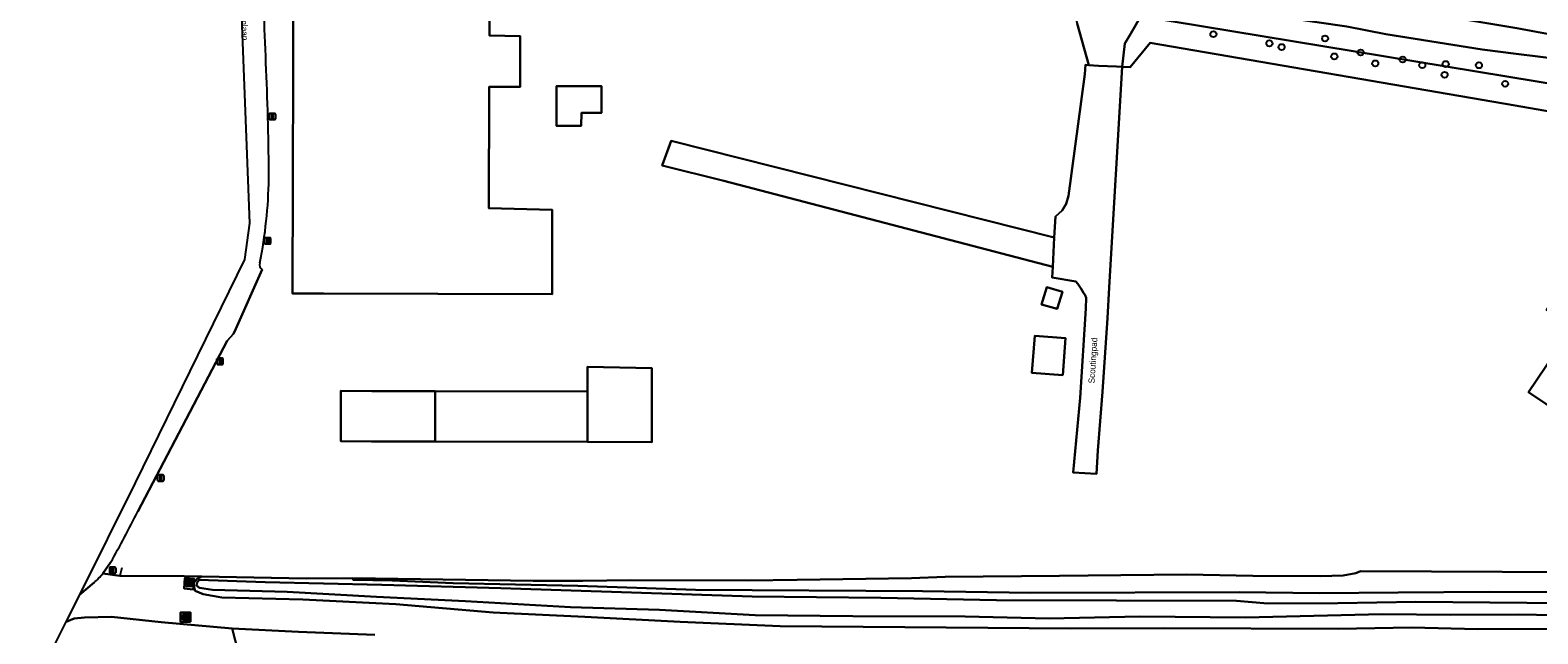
# Model space of a CAD drawing. Extents: x 162156 to 163172, y 378995 to 380779.
# Drawn here: x 162165.5 to 162409.9, y 379596.5 to 379694.4 of the extents above; entities that cross this region are included whole.
import ezdxf

# ---------------------------------------------------------------- set-up
doc = ezdxf.new("R2010")
doc.units = 0
for name, color, linetype in [('IMGEO_Boom', 7, 'Continuous'), ('IMGEO_Erf', 7, 'Continuous'), ('IMGEO_Fietspad_gesloten', 7, 'Continuous'), ('IMGEO_Grasland_overig', 7, 'Continuous'), ('IMGEO_Groenvoorziening', 7, 'Continuous'), ('IMGEO_Hek', 7, 'Continuous'), ('IMGEO_Lichtmast', 7, 'Continuous'), ('IMGEO_Loofbos', 7, 'Continuous'), ('IMGEO_Muur', 7, 'Continuous'), ('IMGEO_Open_loods', 7, 'Continuous'), ('IMGEO_Openbare_ruimte_label', 7, 'Continuous'), ('IMGEO_Pand', 7, 'Continuous'), ('IMGEO_Rijbaan_lokaal_gesloten', 7, 'Continuous'), ('IMGEO_Rijbaan_lokaal_onverhard', 7, 'Continuous'), ('IMGEO_Rijbaan_lokaal_open', 7, 'Continuous'), ('IMGEO_Rioolput', 7, 'Continuous'), ('IMGEO_Terreindeel_open', 7, 'Continuous'), ('IMGEO_Voetpad_open', 7, 'Continuous'), ('IMGEO_Waterloop', 7, 'Continuous')]:
    doc.layers.add(name, color=color, linetype=linetype)

msp = doc.modelspace()

# ---------------------------------------------------------------- linework, layer by layer
at = {"layer": 'IMGEO_Boom'}
for centre in [(162357.34, 379693.7), (162366.41, 379692.22), (162375.45, 379693.01), (162368.4, 379691.61), (162376.94, 379690.1), (162381.21, 379690.74), (162388.02, 379689.6), (162383.58, 379688.97), (162391.2, 379688.68), (162394.81, 379687.12), (162394.99, 379688.86), (162400.38, 379688.66), (162404.63, 379685.66)]:
    msp.add_circle(centre, 0.489, dxfattribs=at)
at = {"layer": 'IMGEO_Erf'}
for points in [[(162240, 379697.22), (162239.99, 379693.48), (162244.97, 379693.37), (162244.95, 379685.17), (162239.96, 379685.18), (162239.96, 379684.79), (162239.91, 379665.52), (162250.18, 379665.21), (162250.14, 379651.57), (162213.07, 379651.67), (162208.07, 379651.68), (162208.22, 379706.6)], [(162422.68, 379679.3), (162406.24, 379682.12), (162347.07, 379692.29), (162343.87, 379688.35), (162342.56, 379688.42), (162340.42, 379652.66), (162340.16, 379647.64), (162339.34, 379635.71), (162338.58, 379626.21), (162338.38, 379622.42), (162334.62, 379622.62), (162335.73, 379634.73), (162336.64, 379649.22), (162336.73, 379650.95), (162336.54, 379651.37), (162336.31, 379651.77), (162335.93, 379652.43), (162335.39, 379653.25), (162335.02, 379653.62), (162331.2, 379654.23), (162331.29, 379655.97), (162277.99, 379669.94), (162268.01, 379672.39), (162269.44, 379676.44), (162331.54, 379660.72), (162331.72, 379664.12), (162332.81, 379665.1), (162333.45, 379666.21), (162333.87, 379667.51), (162336.51, 379687.23), (162336.59, 379688.71), (162337.17, 379688.68), (162335.24, 379695.41)], [(162203.16, 379655.54), (162198.9, 379645.91), (162198.5, 379645.14), (162197.49, 379644), (162183.01, 379616.32)], [(162178.58, 379608.03), (162177.32, 379606.25), (162180.07, 379605.9), (162190.49, 379605.85), (162193.39, 379605.8), (162210.27, 379605.48), (162217.87, 379605.5), (162247.08, 379605.1), (162255.15, 379605.08), (162262.9, 379605.2), (162282.05, 379605.15), (162289.85, 379605.22), (162308.4, 379605.53), (162313.87, 379605.74), (162332.41, 379605.9), (162337.03, 379605.95), (162352.96, 379606.09), (162363.72, 379605.88), (162374.72, 379605.85), (162378.4, 379605.96), (162380.44, 379606.31), (162381.21, 379606.63), (162576.44, 379605.74)]]:
    msp.add_lwpolyline(points, dxfattribs=at)
for points in [[(162254.88, 379678.83), (162250.86, 379678.84), (162250.88, 379685.29), (162258.15, 379685.27), (162258.14, 379680.95), (162254.89, 379680.96)], [(162415.52, 379646.14), (162411.33, 379649.02), (162421.29, 379663.64), (162425.48, 379660.81), (162425.79, 379661.28), (162429.79, 379658.54), (162430.06, 379657.09), (162431.71, 379655.98), (162433.15, 379656.25), (162441.34, 379650.7), (162431.1, 379635.6), (162426.95, 379638.44), (162419.81, 379628), (162408.42, 379635.69)], [(162332.03, 379649.15), (162329.49, 379649.9), (162330.33, 379652.7), (162332.86, 379651.95)], [(162332.92, 379638.41), (162327.93, 379638.8), (162328.4, 379644.79), (162333.38, 379644.4)], [(162266.29, 379627.56), (162255.86, 379627.59), (162231.19, 379627.66), (162220.89, 379627.68), (162215.89, 379627.7), (162215.91, 379635.86), (162220.91, 379635.84), (162231.21, 379635.82), (162255.88, 379635.75), (162255.89, 379639.75), (162266.32, 379639.54)]]:
    msp.add_lwpolyline(points, close=True, dxfattribs=at)
for centre, radius, start, end in [((161851.59, 379678.49), 352.33, 1.5364, 4.4027), ((161695.6, 379666.41), 508.66, 0.4352, 2.4254), ((162126.57, 379671.65), 77.68, 348.8463, 358.9849), ((162203.65, 379656.31), 0.915, 160.322, 237.814), ((161991.49, 379713.35), 214.7, 330.6237, 333.1309)]:
    msp.add_arc(centre, radius, start, end, dxfattribs=at)
at = {"layer": 'IMGEO_Fietspad_gesloten'}
msp.add_lwpolyline([(162293.88, 379713.56), (162297.83, 379712.83), (162406.51, 379694.67), (162426.26, 379691.02), (162431.74, 379689.86)], dxfattribs=at)
at = {"layer": 'IMGEO_Grasland_overig'}
for points in [[(162431.74, 379689.86), (162426.26, 379691.02), (162406.51, 379694.67), (162297.83, 379712.83)], [(162336.99, 379698.76), (162343.52, 379698.34), (162344.24, 379698.95), (162346.34, 379699.64), (162347.96, 379699.34), (162359.67, 379698.01), (162369.63, 379696.28), (162378.99, 379694.93), (162385.27, 379693.71), (162400.92, 379691.22), (162406.42, 379690.54), (162420.47, 379688.81)]]:
    msp.add_lwpolyline(points, dxfattribs=at)
at = {"layer": 'IMGEO_Groenvoorziening'}
for points in [[(162430.28, 379682.33), (162429.51, 379682.78), (162345.56, 379696.61), (162344.76, 379695.24), (162343.93, 379693.83), (162342.98, 379692.21), (162342.56, 379688.42), (162343.87, 379688.35), (162347.07, 379692.29), (162406.24, 379682.12), (162422.68, 379679.3), (162423.76, 379680.09), (162427.17, 379682.58)], [(162192.09, 379604.77), (162191.99, 379603.7), (162190.5, 379603.81), (162190.63, 379605.52), (162192.11, 379605.41)], [(162191.55, 379598.45), (162189.92, 379598.44), (162189.91, 379599.95), (162191.54, 379599.97)], [(162165.54, 379587.07), (162171.56, 379586.89), (162171.57, 379589.2), (162172.13, 379590.83), (162172.89, 379591.55), (162173.82, 379591.75), (162175.52, 379591.81), (162183.9, 379591.47), (162193.2, 379590.46), (162200.18, 379590.02), (162198.3, 379597.35), (162186.78, 379598.4), (162178.75, 379599.23), (162174.33, 379599.15), (162172.66, 379598.95), (162171.36, 379598.45), (162171.31, 379598.43), (162167.11, 379590.02)]]:
    msp.add_lwpolyline(points, close=True, dxfattribs=at)
for points in [[(162175.92, 379604.79), (162173.52, 379602.83), (162171.31, 379598.43), (162171.36, 379598.45), (162172.66, 379598.95), (162174.33, 379599.15), (162178.75, 379599.23), (162186.78, 379598.4), (162198.3, 379597.35), (162209.04, 379596.79), (162221.4, 379596.34)], [(162192.09, 379604.77), (162192.6, 379605.42), (162193.39, 379605.8), (162190.49, 379605.85), (162180.07, 379605.9), (162177.32, 379606.25)], [(162417.45, 379603.23), (162402.03, 379603.27), (162387.27, 379603.21), (162374.55, 379603.06), (162361.54, 379603.25), (162327.73, 379603.12), (162310.18, 379603.38), (162273.39, 379603.64), (162254.33, 379604.29), (162234.09, 379604.68), (162224.23, 379605.14), (162217.88, 379605.23), (162217.87, 379605.5), (162210.27, 379605.48), (162193.39, 379605.8), (162192.6, 379605.42), (162192.09, 379604.77), (162192.12, 379604), (162192.29, 379603.47), (162193.56, 379602.9), (162196.6, 379602.38), (162209.76, 379602.03), (162224.79, 379601.29), (162240.59, 379599.92), (162255.44, 379599.26), (162270.89, 379598.43), (162287.14, 379597.73), (162334.23, 379597.34), (162349.3, 379597.38), (162377.58, 379597.27), (162389.47, 379597.5), (162400.18, 379597.26), (162422.68, 379597.35)], [(162422.68, 379597.35), (162400.18, 379597.26), (162389.47, 379597.5), (162377.58, 379597.27), (162349.3, 379597.38), (162334.23, 379597.34), (162287.14, 379597.73), (162270.89, 379598.43), (162255.44, 379599.26), (162240.59, 379599.92), (162224.79, 379601.29), (162209.76, 379602.03), (162196.6, 379602.38), (162193.56, 379602.9), (162192.29, 379603.47), (162192.12, 379604), (162192.09, 379604.77)], [(162429.76, 379599.2), (162406.83, 379599.61), (162395.85, 379599.58), (162384.71, 379599.68), (162362.52, 379599.13), (162345.43, 379599.3), (162330.73, 379598.97), (162317.12, 379599.28), (162298.89, 379599.34), (162283.05, 379599.52), (162267.53, 379600.4), (162253.15, 379600.81), (162236.09, 379601.8), (162221.69, 379602.47), (162207.2, 379603.27), (162195.11, 379603.61), (162192.98, 379603.96), (162192.5, 379604.34), (162192.59, 379604.82), (162192.93, 379605.24), (162203.62, 379604.86), (162222.57, 379604.41), (162241.81, 379603.9), (162282.56, 379602.52), (162303.45, 379602.33), (162322.16, 379601.93), (162361.11, 379601.84), (162366.19, 379601.41), (162377.5, 379601.47), (162390.14, 379601.66), (162450.09, 379601.12)], [(162576.44, 379605.74), (162381.21, 379606.63), (162380.44, 379606.31), (162378.4, 379605.96), (162374.72, 379605.85), (162363.72, 379605.88), (162352.96, 379606.09), (162337.03, 379605.95), (162332.41, 379605.9), (162313.87, 379605.74), (162308.4, 379605.53), (162289.85, 379605.22), (162282.05, 379605.15), (162262.9, 379605.2), (162255.15, 379605.08), (162247.08, 379605.1), (162217.87, 379605.5), (162217.88, 379605.23), (162224.23, 379605.14), (162234.09, 379604.68), (162254.33, 379604.29), (162273.39, 379603.64), (162310.18, 379603.38), (162327.73, 379603.12), (162361.54, 379603.25), (162374.55, 379603.06), (162387.27, 379603.21), (162402.03, 379603.27), (162417.45, 379603.23)], [(162221.4, 379596.34), (162209.04, 379596.79), (162198.3, 379597.35), (162200.18, 379590.02)]]:
    msp.add_lwpolyline(points, dxfattribs=at)
msp.add_arc((162166.58, 379615.14), 13.94, 312.0389, 320.3631, dxfattribs=at)
at = {"layer": 'IMGEO_Hek'}
for points in [[(162342.56, 379688.42), (162343.87, 379688.35), (162347.07, 379692.29), (162406.24, 379682.12)], [(162337.17, 379688.68), (162338.71, 379688.6)], [(162338.71, 379688.6), (162341.61, 379688.46)], [(162341.61, 379688.46), (162342.56, 379688.42)], [(162406.24, 379682.12), (162422.68, 379679.3), (162423.76, 379680.09)]]:
    msp.add_lwpolyline(points, dxfattribs=at)
at = {"layer": 'IMGEO_Lichtmast'}
for p, q in [((162204.31, 379679.96), (162204.31, 379680.76)), ((162204.31, 379680.76), (162204.31, 379679.96)), ((162204.41, 379680.86), (162205.2, 379680.86)), ((162205.2, 379680.86), (162204.41, 379680.86)), ((162205.3, 379680.76), (162205.3, 379679.96)), ((162205.3, 379679.96), (162205.3, 379680.76)), ((162205.2, 379679.86), (162204.41, 379679.86)), ((162204.41, 379679.86), (162205.2, 379679.86)), ((162203.54, 379659.8), (162203.54, 379660.6)), ((162203.54, 379660.6), (162203.54, 379659.8)), ((162203.64, 379660.7), (162204.42, 379660.7)), ((162204.42, 379660.7), (162203.64, 379660.7)), ((162204.52, 379660.6), (162204.52, 379659.8)), ((162204.52, 379659.8), (162204.52, 379660.6)), ((162204.42, 379659.7), (162203.64, 379659.7)), ((162203.64, 379659.7), (162204.42, 379659.7)), ((162195.8, 379640.26), (162195.8, 379641.06)), ((162195.8, 379641.06), (162195.8, 379640.26)), ((162195.9, 379641.16), (162196.69, 379641.16)), ((162196.69, 379641.16), (162195.9, 379641.16)), ((162196.79, 379641.06), (162196.79, 379640.26)), ((162196.79, 379640.26), (162196.79, 379641.06)), ((162196.69, 379640.16), (162195.9, 379640.16)), ((162195.9, 379640.16), (162196.69, 379640.16)), ((162186.21, 379621.35), (162186.21, 379622.15)), ((162186.21, 379622.15), (162186.21, 379621.35)), ((162186.31, 379622.25), (162187.1, 379622.25)), ((162187.1, 379622.25), (162186.31, 379622.25)), ((162187.2, 379622.15), (162187.2, 379621.35)), ((162187.2, 379621.35), (162187.2, 379622.15)), ((162187.1, 379621.25), (162186.31, 379621.25)), ((162186.31, 379621.25), (162187.1, 379621.25)), ((162178.44, 379606.39), (162178.44, 379607.19)), ((162178.44, 379607.19), (162178.44, 379606.39)), ((162178.54, 379607.29), (162179.33, 379607.29)), ((162179.33, 379607.29), (162178.54, 379607.29)), ((162179.43, 379607.19), (162179.43, 379606.39)), ((162179.43, 379606.39), (162179.43, 379607.19)), ((162179.33, 379606.29), (162178.54, 379606.29)), ((162178.54, 379606.29), (162179.33, 379606.29))]:
    msp.add_line(p, q, dxfattribs=at)
for points in [[(162204.73, 379680.73), (162204.88, 379680.73), (162204.88, 379679.98), (162204.73, 379679.98), (162204.73, 379680.73)], [(162203.96, 379660.57), (162204.11, 379660.57), (162204.11, 379659.82), (162203.96, 379659.82), (162203.96, 379660.57)], [(162196.22, 379641.04), (162196.37, 379641.04), (162196.37, 379640.29), (162196.22, 379640.29), (162196.22, 379641.04)], [(162186.63, 379622.12), (162186.78, 379622.12), (162186.78, 379621.37), (162186.63, 379621.37), (162186.63, 379622.12)], [(162178.86, 379607.16), (162179.01, 379607.16), (162179.01, 379606.41), (162178.86, 379606.41), (162178.86, 379607.16)]]:
    msp.add_lwpolyline(points, dxfattribs=at)
for centre, start, end in [((162204.41, 379680.76), 90, 180), ((162204.41, 379680.76), 90, 180), ((162205.2, 379680.76), 0, 90), ((162205.2, 379680.76), 360, 90), ((162204.41, 379679.96), 180, 270), ((162204.41, 379679.96), 180, 270), ((162205.2, 379679.96), 270, 0), ((162205.2, 379679.96), 270, 0), ((162203.64, 379660.6), 90, 180), ((162203.64, 379660.6), 90, 180), ((162204.42, 379660.6), 0, 90), ((162204.42, 379660.6), 360, 90), ((162203.64, 379659.8), 180, 270), ((162203.64, 379659.8), 180, 270), ((162204.42, 379659.8), 270, 0), ((162204.42, 379659.8), 270, 0), ((162195.9, 379641.06), 90, 180), ((162195.9, 379641.06), 90, 180), ((162196.69, 379641.06), 0, 90), ((162196.69, 379641.06), 360, 90), ((162195.9, 379640.26), 180, 270), ((162195.9, 379640.26), 180, 270), ((162196.69, 379640.26), 270, 0), ((162196.69, 379640.26), 270, 0), ((162186.31, 379622.15), 90, 180), ((162186.31, 379622.15), 90, 180), ((162187.1, 379622.15), 0, 90), ((162187.1, 379622.15), 360, 90), ((162186.31, 379621.35), 180, 270), ((162186.31, 379621.35), 180, 270), ((162187.1, 379621.35), 270, 0), ((162187.1, 379621.35), 270, 0), ((162178.54, 379607.19), 90, 180), ((162178.54, 379607.19), 90, 180), ((162179.33, 379607.19), 0, 90), ((162179.33, 379607.19), 360, 90), ((162178.54, 379606.39), 180, 270), ((162178.54, 379606.39), 180, 270), ((162179.33, 379606.39), 270, 0), ((162179.33, 379606.39), 270, 0)]:
    msp.add_arc(centre, 0.1, start, end, dxfattribs=at)
at = {"layer": 'IMGEO_Loofbos'}
msp.add_lwpolyline([(162420.47, 379688.81), (162406.42, 379690.54), (162400.92, 379691.22), (162385.27, 379693.71), (162378.99, 379694.93), (162369.63, 379696.28), (162359.67, 379698.01), (162347.96, 379699.34), (162346.34, 379699.64), (162344.24, 379698.95), (162343.52, 379698.34), (162346.47, 379698.15), (162345.56, 379696.61), (162429.51, 379682.78)], dxfattribs=at)
at = {"layer": 'IMGEO_Muur'}
for points in [[(162180.39, 379607.19), (162180.07, 379605.9)], [(162180.07, 379605.9), (162190.49, 379605.85), (162210.27, 379605.48), (162217.87, 379605.5), (162247.08, 379605.1), (162255.15, 379605.08), (162262.9, 379605.2), (162282.05, 379605.15), (162289.85, 379605.22), (162308.4, 379605.53), (162313.87, 379605.74), (162332.41, 379605.9)], [(162332.41, 379605.9), (162337.03, 379605.95)], [(162337.03, 379605.95), (162352.96, 379606.09), (162363.72, 379605.88), (162374.72, 379605.85), (162378.4, 379605.96), (162380.44, 379606.31), (162381.21, 379606.63)], [(162381.21, 379606.63), (162576.44, 379605.74), (162576.49, 379606.38)]]:
    msp.add_lwpolyline(points, dxfattribs=at)
at = {"layer": 'IMGEO_Open_loods'}
msp.add_lwpolyline([(162255.88, 379635.75), (162231.21, 379635.82), (162231.19, 379627.66), (162255.86, 379627.59)], close=True, dxfattribs=at)
at = {"layer": 'IMGEO_Pand'}
msp.add_lwpolyline([(162208.22, 379706.6), (162208.07, 379651.68), (162213.07, 379651.67), (162250.14, 379651.57), (162250.18, 379665.21), (162239.91, 379665.52), (162239.96, 379684.79), (162239.96, 379685.18), (162244.95, 379685.17), (162244.97, 379693.37), (162239.99, 379693.48), (162240, 379697.22)], dxfattribs=at)
for points in [[(162258.14, 379680.95), (162258.15, 379685.27), (162250.88, 379685.29), (162250.86, 379678.84), (162254.88, 379678.83), (162254.89, 379680.96)], [(162408.42, 379635.69), (162419.81, 379628), (162426.95, 379638.44), (162431.1, 379635.6), (162441.34, 379650.7), (162433.15, 379656.25), (162431.71, 379655.98), (162430.06, 379657.09), (162429.79, 379658.54), (162425.79, 379661.28), (162425.48, 379660.81), (162421.29, 379663.64), (162411.33, 379649.02), (162415.52, 379646.14)], [(162329.49, 379649.9), (162332.03, 379649.15), (162332.86, 379651.95), (162330.33, 379652.7)], [(162332.92, 379638.41), (162333.38, 379644.4), (162328.4, 379644.79), (162327.93, 379638.8)], [(162266.32, 379639.54), (162255.89, 379639.75), (162255.88, 379635.75), (162255.86, 379627.59), (162266.29, 379627.56)], [(162231.21, 379635.82), (162220.91, 379635.84), (162215.91, 379635.86), (162215.89, 379627.7), (162220.89, 379627.68), (162231.19, 379627.66)]]:
    msp.add_lwpolyline(points, close=True, dxfattribs=at)
at = {"layer": 'IMGEO_Rijbaan_lokaal_gesloten'}
for points in [[(162202.01, 379718.21), (162201.35, 379726.94), (162201.08, 379730.48), (162200.25, 379730.36), (162198.21, 379730.08), (162198.57, 379728.69), (162201.1, 379663.04), (162200.26, 379657.15), (162182.59, 379620.96), (162173.52, 379602.83)], [(162183.01, 379616.32), (162197.49, 379644), (162198.5, 379645.14), (162198.9, 379645.91), (162203.16, 379655.54)], [(162177.32, 379606.25), (162178.58, 379608.03)], [(162173.52, 379602.83), (162175.92, 379604.79)]]:
    msp.add_lwpolyline(points, dxfattribs=at)
for centre, radius, start, end in [((161851.59, 379678.49), 352.33, 1.5364, 4.4027), ((161695.6, 379666.41), 508.66, 0.4352, 2.4254), ((162126.57, 379671.65), 77.68, 348.8463, 358.9849), ((162203.65, 379656.31), 0.915, 160.322, 237.814), ((161991.49, 379713.35), 214.7, 330.6237, 333.1309), ((162166.58, 379615.14), 13.94, 312.0389, 320.3631)]:
    msp.add_arc(centre, radius, start, end, dxfattribs=at)
at = {"layer": 'IMGEO_Rijbaan_lokaal_onverhard'}
msp.add_lwpolyline([(162269.44, 379676.44), (162268.01, 379672.39), (162277.99, 379669.94), (162331.29, 379655.97), (162331.54, 379660.72)], close=True, dxfattribs=at)
at = {"layer": 'IMGEO_Rijbaan_lokaal_open'}
msp.add_lwpolyline([(162342.56, 379688.42), (162341.61, 379688.46), (162338.71, 379688.6), (162337.17, 379688.68), (162336.59, 379688.71), (162336.51, 379687.23), (162333.87, 379667.51), (162333.45, 379666.21), (162332.81, 379665.1), (162331.72, 379664.12), (162331.54, 379660.72), (162331.29, 379655.97), (162331.2, 379654.23), (162335.02, 379653.62), (162335.39, 379653.25), (162335.93, 379652.43), (162336.31, 379651.77), (162336.54, 379651.37), (162336.73, 379650.95), (162336.64, 379649.22), (162335.73, 379634.73), (162334.62, 379622.62), (162338.38, 379622.42), (162338.58, 379626.21), (162339.34, 379635.71), (162340.16, 379647.64), (162340.42, 379652.66)], close=True, dxfattribs=at)
at = {"layer": 'IMGEO_Rioolput'}
for p, q in [((162190.81, 379604.26), (162190.81, 379605.11)), ((162190.89, 379605.18), (162191.74, 379605.18)), ((162191.07, 379604.68), (162191.07, 379604.69)), ((162191.51, 379604.64), (162191.11, 379604.64)), ((162191.12, 379604.73), (162191.51, 379604.73)), ((162191.3, 379604.96), (162191.33, 379604.96)), ((162191.32, 379604.4), (162191.3, 379604.4)), ((162191.56, 379604.69), (162191.56, 379604.68)), ((162191.82, 379605.11), (162191.82, 379604.26)), ((162191.74, 379604.18), (162190.89, 379604.18)), ((162190.3, 379598.76), (162190.3, 379599.62)), ((162190.37, 379599.69), (162191.23, 379599.69)), ((162190.79, 379599.47), (162190.81, 379599.47)), ((162191.3, 379599.62), (162191.3, 379598.76)), ((162191.23, 379598.69), (162190.37, 379598.69)), ((162190.56, 379599.18), (162190.56, 379599.2)), ((162190.6, 379599.23), (162191, 379599.23)), ((162191, 379599.15), (162190.6, 379599.15)), ((162190.81, 379598.91), (162190.79, 379598.91)), ((162191.04, 379599.2), (162191.04, 379599.18))]:
    msp.add_line(p, q, dxfattribs=at)
for points in [[(162190.81, 379604.26), (162190.81, 379605.11)], [(162190.89, 379605.18), (162191.74, 379605.18)], [(162191.82, 379605.11), (162191.82, 379604.26)], [(162191.74, 379604.18), (162190.89, 379604.18)], [(162190.3, 379598.76), (162190.3, 379599.62)], [(162190.37, 379599.69), (162191.23, 379599.69)], [(162191.3, 379599.62), (162191.3, 379598.76)], [(162191.23, 379598.69), (162190.37, 379598.69)]]:
    msp.add_lwpolyline(points, dxfattribs=at)
for centre, radius, start, end in [((162190.89, 379605.11), 0.0765, 91.552, 178.448), ((162190.89, 379605.11), 0.0765, 91.552, 178.448), ((162190.89, 379604.26), 0.0765, 181.552, 268.448), ((162190.89, 379604.26), 0.0765, 181.552, 268.448), ((162191.11, 379604.69), 0.0403, 85.8775, 175.7526), ((162191.11, 379604.68), 0.0366, 178.938, 274.7102), ((162191.52, 379604.69), 0.0386, 1.7309, 96.639), ((162191.51, 379604.68), 0.043, 264.8664, 352.4533), ((162191.74, 379605.11), 0.0765, 1.552, 88.448), ((162191.74, 379605.11), 0.0765, 1.552, 88.448), ((162191.74, 379604.26), 0.0765, 271.552, 358.448), ((162191.74, 379604.26), 0.0765, 271.552, 358.448), ((162190.38, 379599.61), 0.0765, 91.552, 178.448), ((162190.38, 379599.61), 0.0765, 91.552, 178.448), ((162191.22, 379599.61), 0.0765, 1.552, 88.448), ((162191.22, 379599.61), 0.0765, 1.552, 88.448), ((162190.38, 379598.76), 0.0765, 181.552, 268.448), ((162190.38, 379598.76), 0.0765, 181.552, 268.448), ((162190.6, 379599.19), 0.0403, 85.8775, 175.7526), ((162190.6, 379599.18), 0.0366, 178.938, 274.7102), ((162191, 379599.19), 0.0386, 1.7309, 96.639), ((162191, 379599.19), 0.043, 264.8664, 352.4533), ((162191.22, 379598.76), 0.0765, 271.552, 358.448), ((162191.22, 379598.76), 0.0765, 271.552, 358.448)]:
    msp.add_arc(centre, radius, start, end, dxfattribs=at)
for centre, major_axis, ratio, start_param, end_param in [((162191.3, 379604.68), (-0.387, 0.002), 0.722429, 4.712389, 7.853982), ((162191.33, 379604.68), (-0.39, 0.002), 0.717154, 1.570796, 4.712389), ((162190.79, 379599.19), (-0.387, 0.002), 0.722429, 4.712389, 7.853982), ((162190.81, 379599.19), (-0.39, 0.002), 0.717154, 1.570796, 4.712389)]:
    msp.add_ellipse(centre, major_axis=major_axis, ratio=ratio, start_param=start_param, end_param=end_param, dxfattribs=at)
at = {"layer": 'IMGEO_Terreindeel_open'}
for points in [[(162192.11, 379605.41), (162190.63, 379605.52), (162190.5, 379603.81), (162191.99, 379603.7), (162192.09, 379604.77)], [(162191.55, 379598.45), (162191.54, 379599.97), (162189.91, 379599.95), (162189.92, 379598.44)]]:
    msp.add_lwpolyline(points, close=True, dxfattribs=at)
at = {"layer": 'IMGEO_Voetpad_open'}
msp.add_lwpolyline([(162342.56, 379688.42), (162342.98, 379692.21), (162343.93, 379693.83), (162344.76, 379695.24), (162345.56, 379696.61), (162346.47, 379698.15), (162343.52, 379698.34), (162336.99, 379698.76), (162334.22, 379698.94), (162334.72, 379697.2), (162335.24, 379695.41), (162337.17, 379688.68), (162338.71, 379688.6), (162341.61, 379688.46)], close=True, dxfattribs=at)
at = {"layer": 'IMGEO_Waterloop'}
msp.add_lwpolyline([(162450.09, 379601.12), (162390.14, 379601.66), (162377.5, 379601.47), (162366.19, 379601.41), (162361.11, 379601.84), (162322.16, 379601.93), (162303.45, 379602.33), (162282.56, 379602.52), (162241.81, 379603.9), (162222.57, 379604.41), (162203.62, 379604.86), (162192.93, 379605.24), (162192.59, 379604.82), (162192.5, 379604.34), (162192.98, 379603.96), (162195.11, 379603.61), (162207.2, 379603.27), (162221.69, 379602.47), (162236.09, 379601.8), (162253.15, 379600.81), (162267.53, 379600.4), (162283.05, 379599.52), (162298.89, 379599.34), (162317.12, 379599.28), (162330.73, 379598.97), (162345.43, 379599.3), (162362.52, 379599.13), (162384.71, 379599.68), (162395.85, 379599.58), (162406.83, 379599.61), (162429.76, 379599.2)], dxfattribs=at)

# ---------------------------------------------------------------- texts
at = {"layer": 'IMGEO_Openbare_ruimte_label'}
for s, rotation, p in [('Roostenlaan', 272.3502, (162199.57, 379700.18)), ('Scoutingpad', 86.3879, (162338.07, 379637.06))]:
    msp.add_text(s, height=1, rotation=rotation, dxfattribs=at).set_placement(p)

doc.saveas('drawing.dxf')
